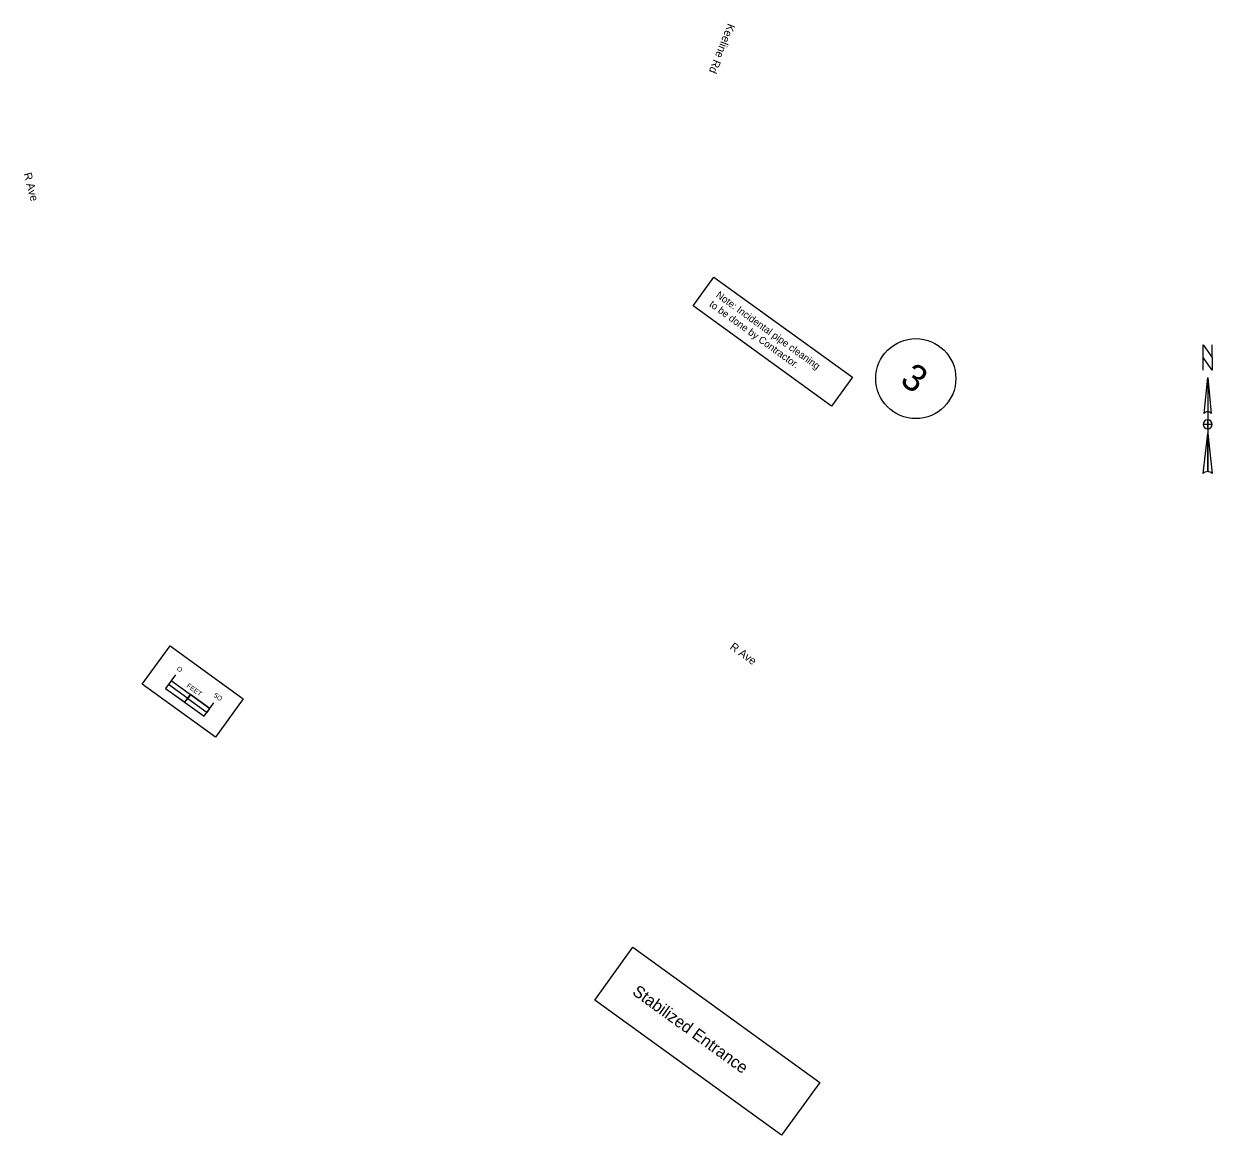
# Model space of a CAD drawing. Extents: x 14314107 to 14315354, y 8681241 to 8682408.
import ezdxf

# ---------------------------------------------------------------- set-up
doc = ezdxf.new("R2010")
doc.units = 0
doc.layers.add('NamedBoundary', color=7, linetype='Continuous')
doc.layers.add('SheetText', color=7, linetype='Continuous')

msp = doc.modelspace()

# ---------------------------------------------------------------- linework, layer by layer
at = {"layer": 'NamedBoundary'}
for p, q in [((14315349.4, 8682037), (14315353.2, 8681999)), ((14315349.4, 8682037), (14315349.4, 8681938.1)), ((14315345.6, 8681999), (14315345.6, 8681999)), ((14315345.8, 8681999.3), (14315346.5, 8682000.1)), ((14315344.7, 8681936.2), (14315349.4, 8681978.1)), ((14315349.4, 8681982.8), (14315349.4, 8681982.8))]:
    msp.add_line(p, q, dxfattribs=at)
for points in [[(14314954.7, 8682006.9), (14314809.5, 8682112.1), (14314831.3, 8682142.3), (14314976.6, 8682037.1)], [(14315354.2, 8682044.6), (14315344.7, 8682057.9), (14315344.7, 8682071.2), (14315354.2, 8682057.9)], [(14314902.2, 8681241.3), (14314706.2, 8681383.2), (14314746.3, 8681438.7), (14314942.3, 8681296.7)]]:
    msp.add_lwpolyline(points, close=True, dxfattribs=at)
for points in [[(14315344.7, 8682044.6), (14315344.7, 8682071.2), (14315354.2, 8682057.9), (14315354.2, 8682071.2)], [(14315345.6, 8681999), (14315349.4, 8682037), (14315349.4, 8682000.9)], [(14315349.4, 8681982.8), (14315349.4, 8681987.6), (14315344.7, 8681987.6)], [(14315354.2, 8681987.6), (14315349.4, 8681987.6), (14315349.4, 8681992.3)], [(14315349.4, 8681938.1), (14315349.4, 8681978.1), (14315354.2, 8681936.2)]]:
    msp.add_lwpolyline(points, dxfattribs=at)
msp.add_circle((14315043.1, 8682035.8), 42, dxfattribs=at)
for centre, radius, start, end in [((14315349.4, 8681996.1), 4.75, 90.0204, 143.1257), ((14315349.4, 8681996.1), 4.75, 36.8481, 90.0218), ((14315349.4, 8681987.6), 4.75, 90, 180), ((14315349.4, 8681987.6), 4.75, 180, 270), ((14315349.4, 8681987.6), 4.75, 0, 90), ((14315349.4, 8681987.6), 4.75, 270, 360), ((14315349.4, 8681931.2), 6.89, 89.9894, 133.619), ((14315349.4, 8681931.2), 6.89, 46.4021, 90.0006)]:
    msp.add_arc(centre, radius, start, end, dxfattribs=at)
at = {"layer": 'SheetText'}
msp.add_line((14314276.1, 8681695.9), (14314281.9, 8681704), dxfattribs=at)
msp.add_line((14314276.1, 8681695.9), (14314281.9, 8681704), dxfattribs=at)
for points in [[(14314260.5, 8681755.3), (14314337.4, 8681699.6), (14314308.1, 8681659.1), (14314231.1, 8681714.8)], [(14314260.5, 8681755.3), (14314337.4, 8681699.6), (14314308.1, 8681659.1), (14314231.1, 8681714.8)], [(14314231.1, 8681714.8), (14314260.5, 8681755.3), (14314337.4, 8681699.6), (14314308.1, 8681659.1)], [(14314255.8, 8681710.5), (14314276.1, 8681695.9), (14314279, 8681700), (14314258.8, 8681714.6)], [(14314279, 8681700), (14314299.3, 8681685.3), (14314302.2, 8681689.3), (14314281.9, 8681704)]]:
    msp.add_lwpolyline(points, close=True, dxfattribs=at)
for points in [[(14314266.1, 8681724.7), (14314255.8, 8681710.5), (14314296.3, 8681681.2), (14314306.6, 8681695.4)], [(14314261.7, 8681718.6), (14314302.2, 8681689.3)]]:
    msp.add_lwpolyline(points, dxfattribs=at)

# ---------------------------------------------------------------- texts
at = {"layer": 'NamedBoundary'}
for s, height, rotation, p in [('Keeline Rd', 8.4, 248.2386, (14314846.1, 8682409.2)), ('R Ave', 8.4, 284.5784, (14314106.8, 8682250.9)), ('Note: Incidental pipe cleaning', 7.5, 324.094, (14314832.7, 8682122)), ('to be done by Contractor.', 7.5, 324.094, (14314825.7, 8682112.3)), ('3', 28, 324.094, (14315025.3, 8682031.4)), ('R Ave', 8.4, 324.094, (14314847.3, 8681752.5)), ('Stabilized Entrance', 12.5, 324.094, (14314744.7, 8681389.8))]:
    msp.add_text(s, height=height, rotation=rotation, dxfattribs=at).set_placement(p)
at = {"layer": 'SheetText'}
for s, p in [('O', (14314267, 8681730.2)), ('FEET', (14314277.4, 8681712.2)), ('5O', (14314305.7, 8681702.2))]:
    msp.add_text(s, height=5, rotation=324.094, dxfattribs=at).set_placement(p)

doc.saveas('drawing.dxf')
